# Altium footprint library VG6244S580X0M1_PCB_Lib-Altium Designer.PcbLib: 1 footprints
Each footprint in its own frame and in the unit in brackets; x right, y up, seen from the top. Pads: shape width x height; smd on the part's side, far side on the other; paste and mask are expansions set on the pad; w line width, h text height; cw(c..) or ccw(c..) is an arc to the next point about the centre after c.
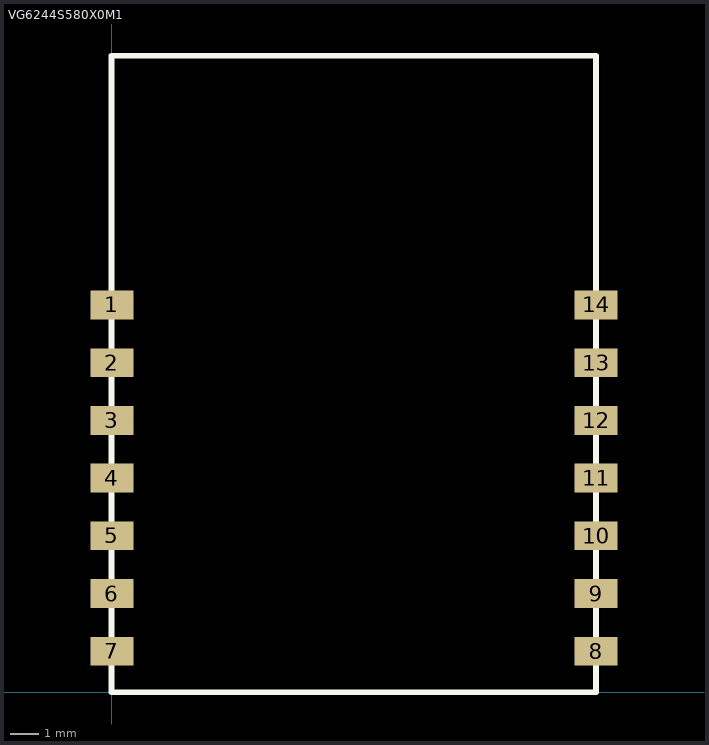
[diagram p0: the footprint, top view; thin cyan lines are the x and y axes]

## VG6244S580X0M1 [mm]
pads (14):
  rect 1.5x1 smd: 1(0.01,13.429) 2(0.01,11.427) 3(0.01,9.426) 4(0.01,7.424) 5(0.01,5.423) 6(0.01,3.421) 7(0.01,1.42) 8(16.802,1.42) 9(16.802,3.421) 10(16.802,5.423) 11(16.802,7.424) 12(16.802,9.426) 13(16.802,11.427) 14(16.802,13.429)
Top Overlay:
  lines w0.2: 0,0 16.8,0 16.8,22.07 0,22.07 0,0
